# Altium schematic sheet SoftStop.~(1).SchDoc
size A
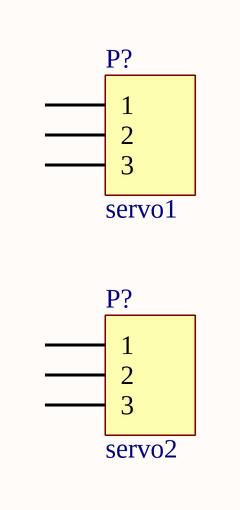
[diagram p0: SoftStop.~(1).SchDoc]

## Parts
(Parts that share a designator on the sheet are numbered #1, #2 ... from top to bottom, then left to right.)
P?#1  servo1  [HDR1X3H]
P?#2  servo2  [HDR1X3H]

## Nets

Not connected (* = marked no-connect by the designer): P?#1 1 2 3; P?#2 1 2 3

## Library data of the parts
P?#1 P?#2 = Header 3H: Header, 3-Pin, Right Angle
